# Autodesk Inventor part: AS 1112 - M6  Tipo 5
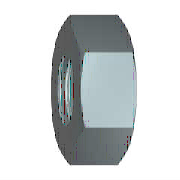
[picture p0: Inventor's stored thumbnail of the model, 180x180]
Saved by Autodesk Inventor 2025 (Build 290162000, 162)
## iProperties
Created: 2024-01
Part Number: AS 1112 - M6  Tipo 5
Material: Acciaio, Dolce
Description: Dadi esagonali metrici ISO, inclusi dadi sottili, dadi con intaglio e dadi a corona
Document SubType Name: Modeling
Standard: AS 1112
Designer: R5800u
Standards Organization: AS
Language: it-IT
Size Designation: M6  Tipo 5
Categories: <MemberInstance><Categories><Category DisplayName="Elementi di fissaggio" InternalName="e4da775c-781d-43d5-af7c-5136215cf5a6" Mnemonic="FSTN"><Category DisplayN
Density: 7.85 g/cm^3
Appearance: Semilucidato
IsCustomPart: 0
Author: R5800u
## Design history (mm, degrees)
body "Solid1"
workaxis "Work Axis1"
workplane "Work Plane1"
sketch "Schizzo1"
  geometry: L1 (-5.774, 0)-(-2.887, 5); L2 (-2.887, 5)-(2.887, 5); L3 (2.887, 5)-(5.774, 0); L4 (5.774, 0)-(2.887, -5); L5 (2.887, -5)-(-2.887, -5); L6 (-2.887, -5)-(-5.774, 0); 2 further points
  constraints: 12 end point, 1 coincident, 1 horizontal, 11 other
  dimensions: "d0" = 11.54701 distance of L3.end L1.start (= 1.1547 x SW)
extrude "Corpo" new body sketch "Schizzo1" distance "d1" = 5.2 (= KOH); taper "d2" = 0 deg
revolve "Smusso1" stored, may be unused: angle "d7" = 90 deg
sketch "Schizzo3"
  geometry: A1 r 5 centre (0, 0) between (-2.5, -4.33) and (2.5, -4.33) reference; 1 further point
  constraints: 1 coincident
hole "Filettatura" sketch "Schizzo3" diameter "d25" = 4.917; stored, may be unused: countersink angle "d29" = 82 deg, drill point angle "d31" = 118 deg; dims "d26" = 6, "d27" = 4, "d28" = 2, "d30" = 8
chamfer "Smusso2" distance "d8" = 0.54127 (= -0.5 x GD1 + 0.5 x NND); stored, may be unused: angle "d9" = 30 deg, second distance "d40" = 0.54127 (= -0.5 x GD1 + 0.5 x NND)
chamfer "Smusso3" distance "d10" = 0.54127 (= -0.5 x GD1 + 0.5 x NND); stored, may be unused: angle "d11" = 30 deg, second distance "d41" = 0.54127 (= -0.5 x GD1 + 0.5 x NND)
sketch "Schizzo2"
  geometry: L1 (0, 2.887)-(0, 5.774) reference; L2 (0, 5.774)-(5.2, 5.774) reference; L3 (5.2, 2.887)-(5.2, 5.774) reference; L4 (-1.04, 0)-(6.24, 0) reference; L5 (0.447, 5.774)-(0, 5); L6 (4.753, 5.774)-(5.2, 5)
  constraints: 4 end point, 4 point on line
  dimensions: "d3" = 30 deg angle of L1 L5 (= ANG1); "d4" = 30 deg angle of L3 L6 (= ANG2); "d5" = 10 diameter of L5.end L4 (= SW0); "d6" = 10 diameter of L6.end L4 (= SW01)
other parameters: "ANG1" = 30 deg [user parameter; used in 1 equation term], "ANG2" = 30 deg [user parameter; used in 1 equation term], "NND" = 6 [user parameter; used in 4 equation terms], "KOH" = 5.2 [user parameter; used in 1 equation term], "SW0" = 10 (= SW) [user parameter; used in 1 equation term], "SW01" = 10 (= SW) [user parameter; used in 1 equation term], "GD1" = 4.91747 (computed from THREADDIA, PTC, TOA) [user parameter; used in 4 equation terms], "d13" = 0, "d14" = 0, "d39" = 0, "d42" = 0, "GUL" = 0.54127 (= 0.541266 x PTC) [user parameter], "WFT" = 0.5 [user parameter], "THREADDIA" = 6 [user parameter; used in 1 equation term], "TOA" = 30 deg [user parameter; used in 1 equation term], "PTC" = 1 [user parameter; used in 4 equation terms], "E0" = 11.55 (= 1.155 x SW) [user parameter], "GAL" = 0.54127 (= 0.541266 x PTC) [user parameter]
